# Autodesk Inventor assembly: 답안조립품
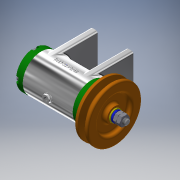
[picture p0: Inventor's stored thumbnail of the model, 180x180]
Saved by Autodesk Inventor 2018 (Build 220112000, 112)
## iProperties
Created: 2020-07
Part Number: 답안조립품
Material: 일반
Document SubType Name: Assembly
Designer: home
Author: home
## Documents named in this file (15)
- C:\Users\home\Desktop\700706V1032\답안조립품.iam
- C:\Users\home\Desktop\700706V1032\본체-01.ipt
- C:\Users\home\Desktop\700706V1032\축.ipt
- C:\Users\home\Desktop\700706V1032\베어링 6002.ipt
- C:\Users\home\Desktop\700706V1032\앞커버.ipt
- C:\Users\home\Desktop\700706V1032\뒤커버.ipt
- C:\Users\home\Desktop\700706V1032\오일 실 15 25 7.ipt
- C:\Users\home\Desktop\700706V1032\볼트 M4x12.ipt
- C:\Users\home\Desktop\700706V1032\Ű 3x3x12.ipt
- C:\Users\home\Desktop\700706V1032\V벨트풀리.ipt
- C:\Users\home\Desktop\700706V1032\와셔 8x17.ipt
- C:\Users\home\Desktop\700706V1032\스프링와셔 8.ipt
- C:\Users\home\Desktop\700706V1032\너트 M8.ipt
- C:\Users\home\Desktop\700706V1032\볼트 M6x8.ipt
- C:\Users\home\Desktop\700706V1032\와셔 6x11.5.ipt
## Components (2 placed, 2 different names)
1. Ű 3x3x12:1
2. V벨트풀리:1
